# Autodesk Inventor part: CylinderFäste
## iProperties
Created: 2007-04
Part Number: CylinderFäste
Document SubType Name: Modeling
Designer: kurs1
Density: 1 g/cm^3
Author: kurs1
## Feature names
1. Extrusion1
2. Hole1
3. Extrusion2
4. Fillet1
